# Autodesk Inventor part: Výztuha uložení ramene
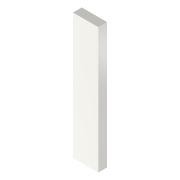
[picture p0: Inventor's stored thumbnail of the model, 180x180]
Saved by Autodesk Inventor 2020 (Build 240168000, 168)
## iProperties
Created: 2025-03
Part Number: Výztuha uložení ramene
Material: Ocel
Document SubType Name: Modeling
Designer: doma
Density: 7.85 g/cm^3
Appearance: Ocel
Mass: 108.33 g
Surface Area: 55.3 cm^2
Volume: 13.8 cm^3
Author: doma
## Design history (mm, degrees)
sketch "Náčrt1"
  geometry: L1 (0, 0)-(23, 0); L2 (23, 0)-(23, 115); L3 (23, 115)-(0, 115); L4 (0, 115)-(0, 0)
  constraints: 8 end point, 2 parallel, 1 horizontal, 1 perpendicular
  dimensions: "d0" = 23 distance of L3.end L2.end; "d1" = 115 distance of L2.end L1.end
extrude "Vysunutí1" new body sketch "Náčrt1" distance "d2" = 8; taper "d3" = 0 deg
node "Těleso1"
